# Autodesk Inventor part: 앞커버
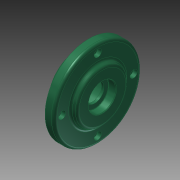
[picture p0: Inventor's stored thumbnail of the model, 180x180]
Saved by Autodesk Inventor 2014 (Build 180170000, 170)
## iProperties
Created: 2015-11
Part Number: 앞커버
Material: 알루미늄 6061
Document SubType Name: Modeling
Designer: mduedu
Density: 2.71 g/cm^3
Mass: 261.017 g
Surface Area: 221.215 cm^2
Volume: 96.3164 cm^3
Appearance: 매끄러움 - 짙은 바다 녹색
Author: mduedu
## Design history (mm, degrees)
sketch "스케치1"
  geometry: C1 r 47.5 at (0, 0); 1 further point
  constraints: 1 centre point, 1 coincident
  dimensions: "d57" = 95 diameter of C1
extrude "돌출1" new body sketch "스케치1" distance "d3" = 10; taper "d4" = 0 deg
sketch "스케치2"
  geometry: C1 r 30 at (0, 0); 1 further point
  constraints: 1 centre point, 1 coincident
  dimensions: "d5" = 60 diameter of C1
extrude "돌출2" join sketch "스케치2" distance "d6" = 5; taper "d7" = -30 deg
sketch "스케치3" dims "d58" = 78
  geometry: 3 further points
  constraints: 2 vertical alignment, 1 coincident, 2 other
hole "구멍1" sketch "스케치3" at (0, 39) diameter "d11" = 4.5; stored, may be unused: countersink angle "d15" = 90 deg, drill point angle "d17" = 118 deg; dims "d12" = 6, "d13" = 8, "d14" = 4.4, "d16" = 8
sketch "스케치4"
  geometry: C1 r 32.5 at (0, 0); 1 further point
  constraints: 1 centre point, 1 coincident
  dimensions: "d21" = 65 diameter of C1
extrude "돌출3" join sketch "스케치4" distance "d23" = 12; taper "d24" = 0 deg
hole "구멍2" diameter "d27" = 34; stored, may be unused: countersink angle "d31" = 90 deg, drill point angle "d33" = 0 deg; dims "d28" = 6, "d29" = 40, "d30" = 12, "d32" = 16, "d68" = 10, "d69" = 10
fillet "모깎기3" dims "d36" = 3
fillet "모깎기4" dims "d37" = 3
fillet "모깎기5" dims "d38" = 0.3
chamfer "모따기1" distance "d39" = 1; stored, may be unused: second distance "d40" = 2, angle "d41" = 45 deg
hole "구멍3" diameter "d44" = 20; stored, may be unused: countersink angle "d48" = 90 deg, drill point angle "d50" = 118 deg; dims "d45" = 6, "d46" = 30, "d47" = 8.3, "d49" = 8, "d59" = 10, "d60" = 10
fillet "모깎기6" dims "d51" = 0.3
chamfer "모따기2" distance "d52" = 0.8; stored, may be unused: second distance "d53" = 2, angle "d54" = 30 deg
node "솔리드1"
pattern_circular "원형 패턴1" dims angle "d19" = 360 deg
